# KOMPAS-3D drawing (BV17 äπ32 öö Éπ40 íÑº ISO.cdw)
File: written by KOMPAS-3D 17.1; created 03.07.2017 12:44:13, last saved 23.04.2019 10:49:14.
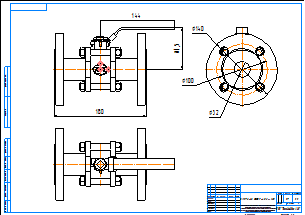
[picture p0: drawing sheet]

Sheet 1: A2, landscape

Title block, sheet 1: name: BV17 Ду32 ФФ Ру40 без ISO; material: Внимание! Данный продукт является объектом авторского права ООО «Торговый Дом АДЛ». / Запрещается изменение, копирование, распространение / (в том числе путем копирования на другие сайты и ресурсы в Интернете) / или любое иное использование информации и объектов без предварительного / согласия правообладателя (ООО «Торговый Дом АДЛ»).; mass: 1,7; sheets: 1; organisation: ООО "Торговый дом АДЛ"; sheet format: A2; stored path: C:\Users\kka\KOMPAS_Work\!Trash\СС02 СС03 ФФ Смотровые стекла\СС01.cdw

Views: Спереди 1, Проекционный вид 2, Проекционный вид 3
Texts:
  Klimkovich
  ADL
Dimensions and other numbers on the sheet: 180; 144; 81,5; 100; 140; 32; 1:1; 1; 1,7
